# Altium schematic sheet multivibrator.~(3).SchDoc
size 431 x 279 mm; SheetNumber: 1; SheetTotal: 1; ENG_APP_DATE: --/--/--; DSN_APP_DATE: --/--/--; CHK_APP_DATE: --/--/--
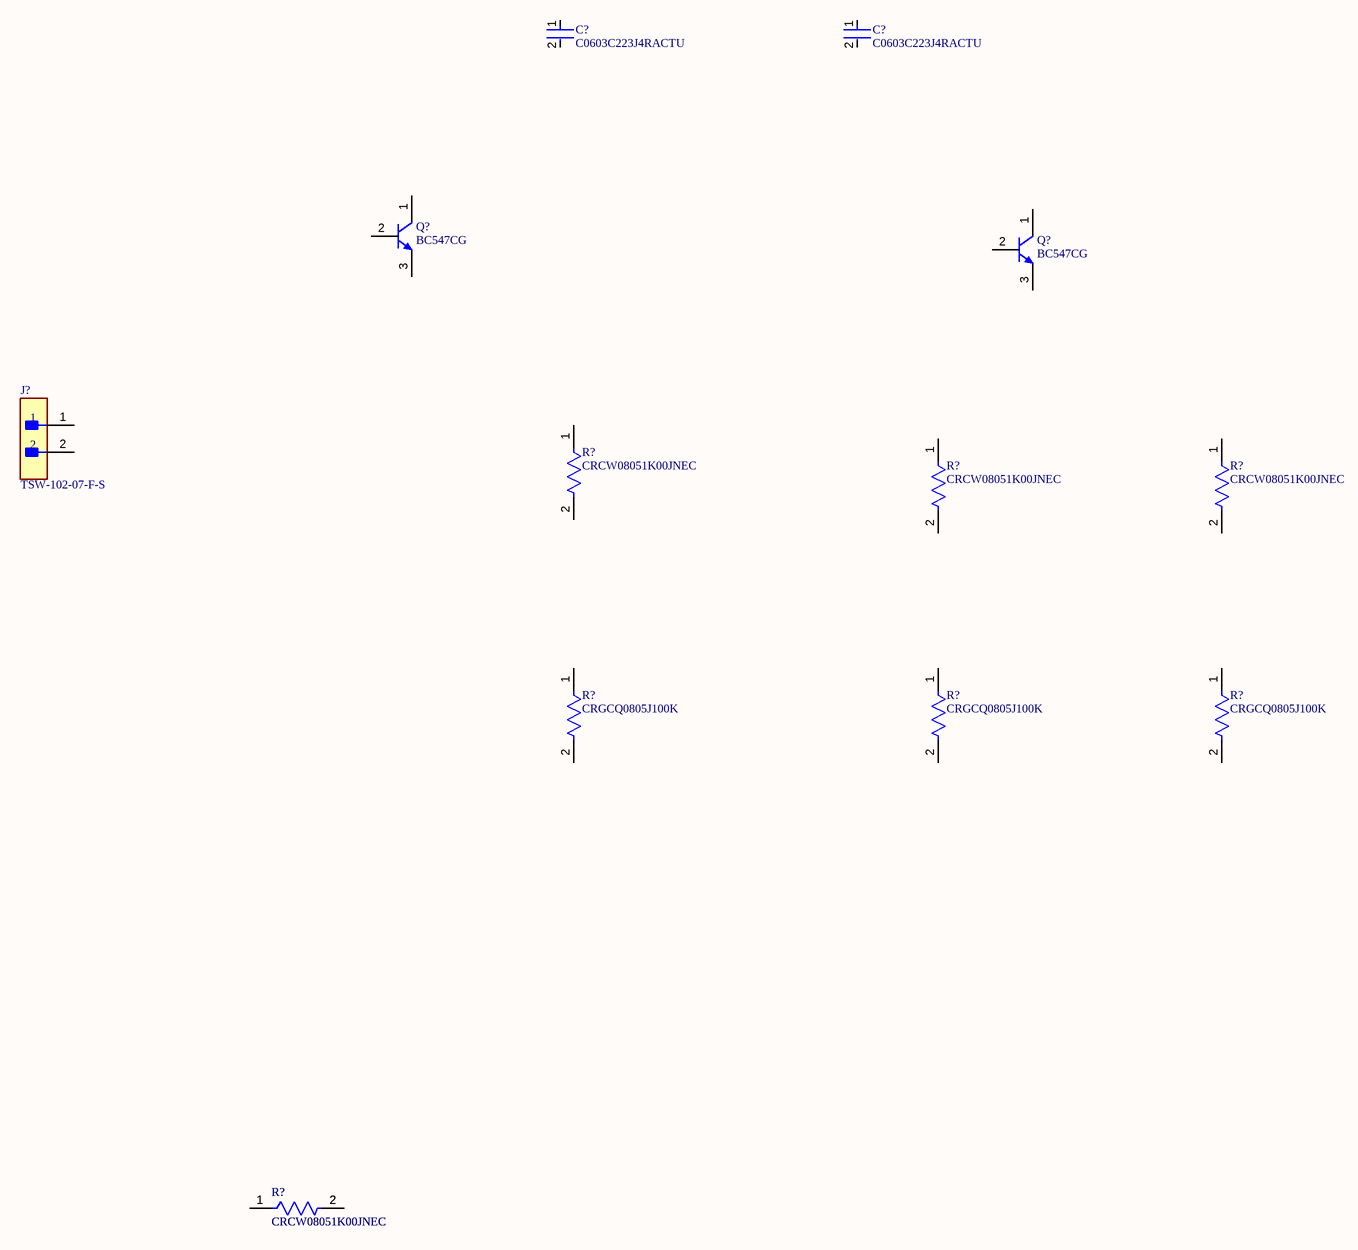
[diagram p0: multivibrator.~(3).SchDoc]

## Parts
(Parts that share a designator on the sheet are numbered #1, #2 ... from top to bottom, then left to right.)
C?#1  C0603C223J4RACTU  [FP-C0603C-CF-MFG]
C?#2  C0603C223J4RACTU  [FP-C0603C-CF-MFG]
J?  TSW-102-07-F-S  [FP-TSW-102-07-F-S-MFG]
Q?#1  BC547CG  [ONSC-TO-92-3-29-11]
Q?#2  BC547CG  [ONSC-TO-92-3-29-11]
R?#1  CRCW08051K00JNEC  [FP-CRCW0805-e3-IPC_A]
R?#2  CRCW08051K00JNEC  [FP-CRCW0805-e3-IPC_A]
R?#3  CRCW08051K00JNEC  [FP-CRCW0805-e3-IPC_A]
R?#4  CRGCQ0805J100K  [FP-CRGCQ0805-IPC_C]
R?#5  CRGCQ0805J100K  [FP-CRGCQ0805-IPC_C]
R?#6  CRGCQ0805J100K  [FP-CRGCQ0805-IPC_C]
R?#7  CRCW08051K00JNEC  [FP-CRCW0805-e3-IPC_A]
R?#8  CRCW08051K00JNEC  [FP-CRCW0805-e3-IPC_A]

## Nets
NetR?#7_1: R?#7.1 R?#8.1
NetR?#7_2: R?#7.2 R?#8.2

Not connected (* = marked no-connect by the designer): C?#1 1 2; C?#2 1 2; J? 1 2; Q?#1 1(C) 2(B) 3(E); Q?#2 1(C) 2(B) 3(E); R?#1 1 2; R?#2 1 2; R?#3 1 2; R?#4 1 2; R?#5 1 2; R?#6 1 2

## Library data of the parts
C?#1 C?#2 = CMP-2006-03745-2: CAP CER 0.022UF 16V 5% X7R 0603; Manufacturer: KEMET; Tolerance: 0.05; Automotive Grade: Grade 1; Temperature Coefficient: 30ppm/°C; Description: C0603 22,000 pF X7R 30ppm/°C 5.00% 16 V; Capacitance: 22,000 pF; Material: Ceramic; Value: 22,000 pF
J? = CMP-02766-001458-1: CONN HEADER VERT 2POS 2.54MM; Gender: Male; Max Current Rating: 7.6A; Number of Contacts: 2; Max Voltage Rating (AC): 550V
Q?#1 Q?#2 = CMP-1048-01464-1: Amplifier Transistor, NPN Silicon, 3-Pin TO-92, Pb-Free, Bulk Box; Manufacturer: On Semiconductor; IC Continuous (A): 0.1; fT Min (MHz): 150
R?#1-R?#3 R?#7 R?#8 = CMP-02407-005778-1: RES Thick Film, 1kΩ, 5%, 0.125W, 200ppm/°C, 0805; Max Power Dissipation: 125mW; Resistance: 1kR
R?#4-R?#6 = CMP-03211-009742-1: CRGCQ0805 100KΩ 0.125W ±100ppm/°C 5% 150V; Manufacturer: TE Connectivity; Tolerance: 0.05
